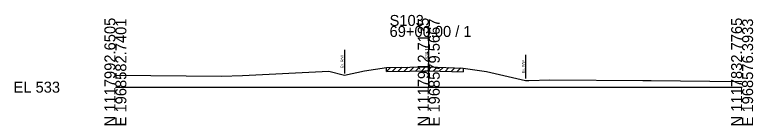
# Model space of a CAD drawing. Extents: x -26 to 163, y -10 to 24018.
# Drawn here: x -25.7 to 162.8, y 16990.3 to 17018.4 of the extents above; entities that cross this region are included whole.
import ezdxf

# ---------------------------------------------------------------- set-up
doc = ezdxf.new("R2010")
doc.units = 0
for name, color, linetype in [('RD_GPK_XS_Cell', 7, 'Continuous'), ('RD_XS_ExGround', 7, 'Continuous'), ('RD_XS_ExPaveRet', 7, 'Continuous'), ('RD_XS_ExRW', 7, 'Continuous'), ('RD_XS_TX_Elev_EX', 7, 'Continuous')]:
    doc.layers.add(name, color=color, linetype=linetype)

msp = doc.modelspace()

# ---------------------------------------------------------------- linework, layer by layer
at = {"layer": 'RD_GPK_XS_Cell'}
for p, q in [((80, 17000), (80, 17015.6)), ((0, 17000), (80, 17000)), ((80, 17000), (160, 17000))]:
    msp.add_line(p, q, dxfattribs=at)
at = {"layer": 'RD_XS_ExGround'}
msp.add_lwpolyline([(0, 17003.06), (27.05, 17002.78), (32.49, 17003), (54.5, 17004.04), (58.45, 17003.02), (63.58, 17004.2), (69.19, 17004.97), (75.2, 17005.11), (78.99, 17005.2), (80, 17005.17), (88.78, 17004.87), (94.7, 17004.01), (104.7, 17001.72), (105.58, 17001.74), (110.91, 17001.86), (134.62, 17001.67), (136.81, 17001.66), (151.72, 17001.51), (160, 17001.44)], dxfattribs=at)
at = {"layer": 'RD_XS_ExPaveRet'}
for p, q in [((69.19, 17003.97), (70.21, 17004.99)), ((69.19, 17003.97), (69.19, 17004.97)), ((69.19, 17003.97), (75.2, 17004.11)), ((70.69, 17004), (71.71, 17005.03)), ((72.19, 17004.04), (73.21, 17005.06)), ((73.69, 17004.07), (74.71, 17005.1)), ((75.19, 17004.11), (76.21, 17005.13)), ((75.2, 17004.11), (78.99, 17004.2)), ((76.69, 17004.14), (77.71, 17005.17)), ((78.19, 17004.18), (79.2, 17005.19)), ((78.99, 17004.2), (80, 17004.17)), ((79.69, 17004.18), (80.66, 17005.14)), ((80, 17004.17), (88.78, 17003.87)), ((81.19, 17004.12), (82.16, 17005.09)), ((82.69, 17004.07), (83.66, 17005.04)), ((84.19, 17004.02), (85.16, 17004.99)), ((85.69, 17003.97), (86.66, 17004.94)), ((87.19, 17003.92), (88.16, 17004.89)), ((88.78, 17004.87), (88.78, 17003.87))]:
    msp.add_line(p, q, dxfattribs=at)
at = {"layer": 'RD_XS_ExRW'}
for p, q in [((58.45, 17009.52), (58.45, 17003.52)), ((104.7, 17008.22), (104.7, 17002.22))]:
    msp.add_line(p, q, dxfattribs=at)

# ---------------------------------------------------------------- texts
at = {"layer": 'RD_GPK_XS_Cell'}
for s, p in [('N 1117992.6505', (0, 16990)), ('E 1968582.7401', (2.8, 16990)), ('N 1117912.7135', (80, 16990)), ('E 1968579.5667', (82.8, 16990)), ('N 1117832.7765', (160, 16990)), ('E 1968576.3933', (162.8, 16990))]:
    msp.add_text(s, height=2.8, rotation=90, dxfattribs=at).set_placement(p)
for s, p in [('S103', (70, 17015.6)), ('69+00.00 / 1', (70, 17012.8)), ('EL 533', (-26, 16998.6))]:
    msp.add_text(s, height=2.8, dxfattribs=at).set_placement(p)
at = {"layer": 'RD_XS_ExRW'}
for p in [(58.2, 17004.87), (104.45, 17003.57)]:
    msp.add_text('Ex. R/W ', height=0.65, rotation=90, dxfattribs=at).set_placement(p)
at = {"layer": 'RD_XS_TX_Elev_EX'}
msp.add_text('538.17', height=0.8, rotation=90, dxfattribs=at).set_placement((79.9, 17007.17))

doc.saveas('drawing.dxf')
